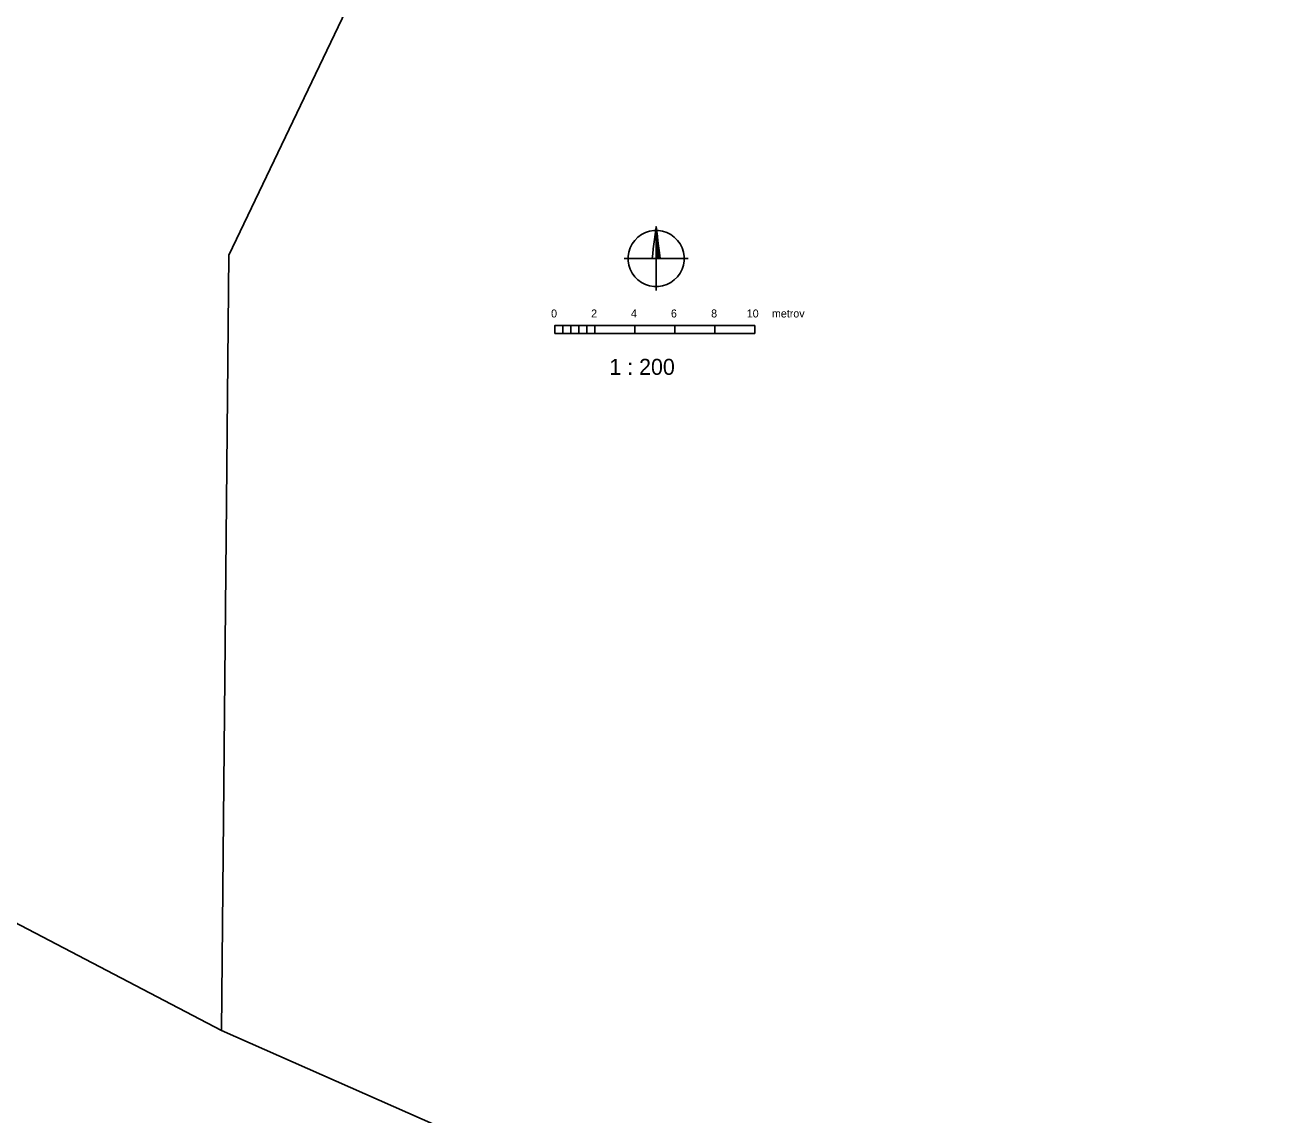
# Model space of a CAD drawing. Extents: x -439750 to -439180, y -1258684 to -1258308.
# Drawn here: x -439607.3 to -439544.4, y -1258565.3 to -1258510.9 of the extents above; entities that cross this region are included whole.
import ezdxf

# ---------------------------------------------------------------- set-up
doc = ezdxf.new("R2010")
doc.units = 0
for name, color, linetype in [('KATASTER', 7, 'Continuous'), ('MIERKA', 7, 'Continuous'), ('SEVER', 7, 'Continuous')]:
    doc.layers.add(name, color=color, linetype=linetype)

# ---------------------------------------------------------------- blocks, each defined once
blk = doc.blocks.new('SEVER')
for points in [[(0.55, 6.98), (1.63, 6.81), (2.67, 6.47), (3.65, 5.97), (4.54, 5.32), (5.32, 4.54), (5.97, 3.65), (6.47, 2.67), (6.81, 1.63), (6.98, 0.55), (6.98, -0.55), (6.81, -1.63), (6.47, -2.67), (5.97, -3.65), (5.32, -4.54), (4.54, -5.32), (3.65, -5.97), (2.67, -6.47), (1.63, -6.81), (0.55, -6.98), (-0.55, -6.98), (-1.63, -6.81), (-2.67, -6.47), (-3.65, -5.97), (-4.54, -5.32), (-5.32, -4.54), (-5.97, -3.65), (-6.47, -2.67), (-6.81, -1.63), (-6.98, -0.55), (-6.98, 0.55), (-6.81, 1.63), (-6.47, 2.67), (-5.97, 3.65), (-5.32, 4.54), (-4.54, 5.32), (-3.65, 5.97), (-2.67, 6.47), (-1.63, 6.81), (-0.55, 6.98), (0.55, 6.98)], [(-1, 0), (-0.85, 1.2), (-0.7, 2.4), (-0.55, 3.6), (-0.4, 4.8), (-0.25, 6), (-0.1, 7.2), (0, 8), (0.15, 6.8), (0.3, 5.6), (0.45, 4.4), (0.6, 3.2), (0.75, 2), (0.9, 0.8), (1, 0), (0.92, 0.08), (0.92, 0.56), (0.84, 1.2), (0.84, 0.08), (0.76, 0.08), (0.76, 1.35), (0.76, 1.84), (0.68, 2.48), (0.68, 1.21), (0.68, 0.08), (0.6, 0.08), (0.6, 1.35), (0.6, 2.62), (0.6, 3.12), (0.52, 3.68), (0.52, 2.41), (0.52, 1.14), (0.52, 0.08), (0.44, 0.08), (0.44, 1.35), (0.44, 2.62), (0.44, 3.89), (0.44, 4.32), (0.36, 5.04), (0.36, 3.77), (0.36, 2.5), (0.36, 1.23), (0.36, 0.08), (0.28, 0.08), (0.28, 1.35), (0.28, 2.62), (0.28, 3.89), (0.28, 5.16), (0.28, 5.6), (0.2, 6.32), (0.2, 5.05), (0.2, 3.78), (0.2, 2.51), (0.2, 1.24), (0.2, 0.08), (0.12, 0.08), (0.12, 1.35), (0.12, 2.62), (0.12, 3.89), (0.12, 5.16), (0.12, 6.43), (0.12, 6.96), (0.04, 7.6), (0.04, 6.33), (0.04, 5.06), (0.04, 3.79), (0.04, 2.52), (0.04, 1.25), (0.04, 0.08)], [(0, 8), (0, 6.73), (0, 5.46), (0, 4.19), (0, 2.92), (0, 1.65), (0, 0.38), (0, -0.89), (0, -2.16), (0, -3.43), (0, -4.7), (0, -5.97), (0, -7.24), (0, -8)], [(8, 0), (6.73, 0), (5.46, 0), (4.19, 0), (2.92, 0), (1.65, 0), (0.38, 0), (-0.89, 0), (-2.16, 0), (-3.43, 0), (-4.7, 0), (-5.97, 0), (-7.24, 0), (-8, 0)]]:
    blk.add_lwpolyline(points)

msp = doc.modelspace()

# ---------------------------------------------------------------- linework, layer by layer
at = {"layer": 'KATASTER'}
for points in [[(-439658.88, -1258489.54), (-439635.72, -1258471.93), (-439620.34, -1258480.81), (-439606.15, -1258484.83), (-439591.03, -1258485.49), (-439564.69, -1258504.32), (-439589.36, -1258506.21), (-439597.08, -1258522.38), (-439597.45, -1258561.13), (-439640.46, -1258538.63)], [(-439640.46, -1258538.63), (-439597.45, -1258561.13), (-439567.51, -1258574.36), (-439550.54, -1258581.84), (-439518.67, -1258591.95), (-439482.75, -1258611.76), (-439438.12, -1258627.38), (-439494.8, -1258628.92), (-439535.34, -1258619.8), (-439542.1, -1258617.55), (-439560.33, -1258610.77), (-439586.79, -1258602.08), (-439605.4, -1258593.99), (-439611.21, -1258589.93), (-439618.29, -1258580.27), (-439631.04, -1258560.29)]]:
    msp.add_lwpolyline(points, close=True, dxfattribs=at)
for points in [[(-439548.5, -1258497.7), (-439538.17, -1258484.88), (-439520.19, -1258486.95), (-439507.21, -1258497.49), (-439484.47, -1258496.42), (-439400.54, -1258499.28), (-439387.09, -1258499.74), (-439411.19, -1258562.66), (-439413.56, -1258566.65), (-439437.77, -1258626.82), (-439438.12, -1258627.38), (-439482.75, -1258611.76), (-439518.67, -1258591.95), (-439550.54, -1258581.84), (-439567.51, -1258574.36), (-439597.45, -1258561.13)], [(-439597.45, -1258561.13), (-439597.08, -1258522.38), (-439589.36, -1258506.21), (-439564.69, -1258504.32), (-439548.5, -1258497.7)]]:
    msp.add_lwpolyline(points, dxfattribs=at)
at = {"layer": 'MIERKA'}
msp.add_line((-439570.785, -1258526.289), (-439570.785, -1258525.889), dxfattribs=at)
for points in [[(-439580.385, -1258526.289), (-439580.785, -1258526.289), (-439580.785, -1258525.889), (-439580.385, -1258525.889)], [(-439579.985, -1258526.289), (-439580.385, -1258526.289), (-439580.385, -1258525.889), (-439579.985, -1258525.889)], [(-439579.585, -1258526.289), (-439579.985, -1258526.289), (-439579.985, -1258525.889), (-439579.585, -1258525.889)], [(-439579.185, -1258526.289), (-439579.585, -1258526.289), (-439579.585, -1258525.889), (-439579.185, -1258525.889)], [(-439578.785, -1258526.289), (-439579.185, -1258526.289), (-439579.185, -1258525.889), (-439578.785, -1258525.889)], [(-439576.785, -1258526.289), (-439578.785, -1258526.289), (-439578.785, -1258525.889), (-439576.785, -1258525.889)], [(-439574.785, -1258526.289), (-439576.785, -1258526.289), (-439576.785, -1258525.889), (-439574.785, -1258525.889)], [(-439572.785, -1258526.289), (-439574.785, -1258526.289), (-439574.785, -1258525.889), (-439572.785, -1258525.889)], [(-439570.785, -1258526.289), (-439572.785, -1258526.289), (-439572.785, -1258525.889), (-439570.785, -1258525.889)]]:
    msp.add_lwpolyline(points, dxfattribs=at)

# ---------------------------------------------------------------- block references
at = {"layer": 'SEVER', "xscale": 0.2, "yscale": 0.20000000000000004}
msp.add_blockref('SEVER', (-439575.725, -1258522.544), dxfattribs=at)

# ---------------------------------------------------------------- texts
at = {"layer": 'MIERKA'}
for s, p in [('0', (-439580.975, -1258525.489)), ('2', (-439578.975, -1258525.489)), ('4', (-439576.985, -1258525.489)), ('6', (-439574.985, -1258525.489)), ('8', (-439572.975, -1258525.489)), ('10', (-439571.195, -1258525.489)), ('metrov', (-439569.937, -1258525.489))]:
    msp.add_text(s, height=0.4, dxfattribs=at).set_placement(p)
at = {"layer": 'SEVER'}
msp.add_text('1 : 200', height=0.8, dxfattribs=at).set_placement((-439578.063, -1258528.357))

doc.saveas('drawing.dxf')
